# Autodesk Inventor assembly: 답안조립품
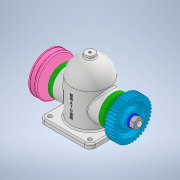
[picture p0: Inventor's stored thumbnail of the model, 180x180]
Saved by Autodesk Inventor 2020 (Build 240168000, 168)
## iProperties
Created: 2021-07
Part Number: 답안조립품
Document SubType Name: Assembly
Designer: Owner
Author: Owner
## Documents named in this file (14)
- C:\Users\Owner\Desktop\710716V1005\답안조립품.iam
- C:\Users\Owner\Desktop\710716V1005\본체.ipt
- C:\Users\Owner\Desktop\710716V1005\V-벨트풀리.ipt
- V-벨트풀리.ipt
- C:\Users\Owner\Desktop\710716V1005\너트 M12x1.25.ipt
- C:\Users\Owner\Desktop\710716V1005\베어링 6203.ipt
- C:\Users\Owner\Desktop\710716V1005\볼트 M4.ipt
- C:\Users\Owner\Desktop\710716V1005\부시.ipt
- C:\Users\Owner\Desktop\710716V1005\스퍼기어.ipt
- C:\Users\Owner\Desktop\710716V1005\오일 실 26 38 8.ipt
- C:\Users\Owner\Desktop\710716V1005\와셔 12x24.ipt
- C:\Users\Owner\Desktop\710716V1005\축.ipt
- C:\Users\Owner\Desktop\710716V1005\커버.ipt
- C:\Users\Owner\Desktop\710716V1005\키 5x5x12.ipt
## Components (1 placed, 1 different names)
1. V-벨트풀리:1
